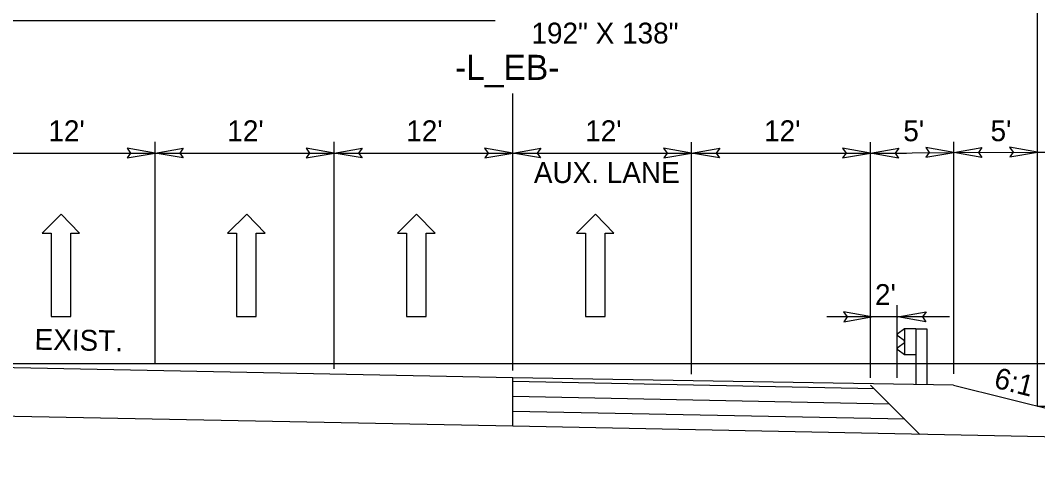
# Model space of a CAD drawing. Extents: x 1727387 to 1728895, y 539219 to 540208.
# Drawn here: x 1727576.9 to 1727645.2, y 539490.3 to 539520.1 of the extents above; entities that cross this region are included whole.
import ezdxf

# ---------------------------------------------------------------- set-up
doc = ezdxf.new("R2010")
doc.units = 0
for name, color, linetype in [('Default', 7, 'Continuous'), ('Prop Dimension Text', 7, 'Continuous'), ('Typical Pavement Slope CELL', 7, 'Continuous'), ('Typical Pavement Slope Information CELL', 7, 'Continuous'), ('Typical Text Centerline CELL', 7, 'Continuous'), ('Typical Text General CELL', 7, 'Continuous')]:
    doc.layers.add(name, color=color, linetype=linetype)

msp = doc.modelspace()

# ---------------------------------------------------------------- linework, layer by layer
at = {"layer": 'Default'}
for p, q in [((1727481.192, 539520.117), (1727608.748, 539520.117)), ((1727609.926, 539496.633), (1727609.926, 539515.213)), ((1727585.93, 539497.114), (1727585.93, 539511.981)), ((1727597.939, 539496.756), (1727597.939, 539511.975)), ((1727609.926, 539496.633), (1727609.926, 539511.975)), ((1727621.935, 539496.393), (1727621.935, 539511.95)), ((1727633.944, 539496.393), (1727633.944, 539511.95)), ((1727633.944, 539496.153), (1727633.944, 539511.95)), ((1727639.53, 539496.417), (1727639.53, 539511.974)), ((1727573.921, 539511.211), (1727585.93, 539511.211)), ((1727585.93, 539511.211), (1727597.939, 539511.211)), ((1727597.939, 539511.211), (1727609.948, 539511.211)), ((1727609.948, 539511.211), (1727621.956, 539511.211)), ((1727621.956, 539511.211), (1727633.965, 539511.211)), ((1727621.956, 539511.211), (1727633.965, 539511.211)), ((1727633.945, 539511.21), (1727639.53, 539511.253)), ((1727633.965, 539511.211), (1727636.345, 539511.211)), ((1727639.57, 539511.246), (1727645.155, 539511.289)), ((1727645.155, 539511.289), (1727661.125, 539511.259)), ((1727579.621, 539507.115), (1727578.341, 539505.855)), ((1727580.861, 539505.855), (1727579.621, 539507.115)), ((1727592.072, 539507.115), (1727590.792, 539505.855)), ((1727593.312, 539505.855), (1727592.072, 539507.115)), ((1727603.472, 539507.115), (1727602.192, 539505.855)), ((1727604.712, 539505.855), (1727603.472, 539507.115)), ((1727615.481, 539507.115), (1727614.201, 539505.855)), ((1727616.721, 539505.855), (1727615.481, 539507.115)), ((1727578.341, 539505.855), (1727578.941, 539505.855)), ((1727578.941, 539505.855), (1727578.941, 539500.255)), ((1727580.261, 539500.255), (1727580.261, 539505.855)), ((1727580.261, 539505.855), (1727580.861, 539505.855)), ((1727590.792, 539505.855), (1727591.392, 539505.855)), ((1727591.392, 539505.855), (1727591.392, 539500.255)), ((1727592.712, 539500.255), (1727592.712, 539505.855)), ((1727592.712, 539505.855), (1727593.312, 539505.855)), ((1727602.192, 539505.855), (1727602.792, 539505.855)), ((1727602.792, 539505.855), (1727602.792, 539500.255)), ((1727604.112, 539500.255), (1727604.112, 539505.855)), ((1727604.112, 539505.855), (1727604.712, 539505.855)), ((1727614.201, 539505.855), (1727614.801, 539505.855)), ((1727614.801, 539505.855), (1727614.801, 539500.255)), ((1727616.121, 539500.255), (1727616.121, 539505.855)), ((1727616.121, 539505.855), (1727616.721, 539505.855)), ((1727635.725, 539496.153), (1727635.725, 539501.028)), ((1727578.941, 539500.255), (1727580.261, 539500.255)), ((1727591.392, 539500.255), (1727592.712, 539500.255)), ((1727602.792, 539500.255), (1727604.112, 539500.255)), ((1727614.801, 539500.255), (1727616.121, 539500.255)), ((1727639.235, 539500.228), (1727630.998, 539500.228)), ((1727653.649, 539497.076), (1727481.192, 539497.076)), ((1727645.155, 539494.248), (1727653.649, 539494.248))]:
    msp.add_line(p, q, dxfattribs=at)
for points in [[(1727584.054, 539510.888), (1727585.93, 539511.211), (1727584.044, 539511.544), (1727584.284, 539511.211)], [(1727587.805, 539510.888), (1727585.93, 539511.211), (1727587.816, 539511.544), (1727587.576, 539511.211)], [(1727596.063, 539510.888), (1727597.939, 539511.211), (1727596.053, 539511.544), (1727596.292, 539511.211)], [(1727599.814, 539510.888), (1727597.939, 539511.211), (1727599.825, 539511.544), (1727599.585, 539511.211)], [(1727608.05, 539510.888), (1727609.926, 539511.211), (1727608.04, 539511.544), (1727608.279, 539511.211)], [(1727611.801, 539510.888), (1727609.926, 539511.211), (1727611.812, 539511.544), (1727611.572, 539511.211)], [(1727620.059, 539510.888), (1727621.935, 539511.211), (1727620.049, 539511.544), (1727620.288, 539511.211)], [(1727623.81, 539510.888), (1727621.935, 539511.211), (1727623.821, 539511.544), (1727623.581, 539511.211)], [(1727632.068, 539510.888), (1727633.944, 539511.211), (1727632.058, 539511.544), (1727632.297, 539511.211)], [(1727635.821, 539510.887), (1727633.945, 539511.21), (1727635.831, 539511.544), (1727635.592, 539511.21)], [(1727637.651, 539510.935), (1727639.527, 539511.258), (1727637.641, 539511.591), (1727637.88, 539511.258)], [(1727641.406, 539510.93), (1727639.53, 539511.253), (1727641.416, 539511.586), (1727641.177, 539511.253)], [(1727643.279, 539510.966), (1727645.155, 539511.289), (1727643.269, 539511.622), (1727643.509, 539511.289)], [(1727632.139, 539499.905), (1727634.014, 539500.228), (1727632.128, 539500.562), (1727632.368, 539500.228)], [(1727637.659, 539499.905), (1727635.783, 539500.228), (1727637.669, 539500.562), (1727637.429, 539500.228)]]:
    msp.add_lwpolyline(points, close=True, dxfattribs=at)
at = {"layer": 'Typical Pavement Slope CELL'}
for p, q in [((1727609.926, 539496.14), (1727563.08, 539497.076)), ((1727609.926, 539492.892), (1727609.926, 539496.14)), ((1727639.512, 539495.659), (1727609.926, 539496.14)), ((1727634.195, 539495.407), (1727609.926, 539495.893)), ((1727633.944, 539495.659), (1727637.258, 539492.345)), ((1727639.512, 539495.659), (1727661.124, 539490.256)), ((1727635.215, 539494.387), (1727609.926, 539494.893)), ((1727597.268, 539493.145), (1727563.08, 539493.829)), ((1727636.236, 539493.366), (1727609.926, 539493.892)), ((1727609.926, 539492.892), (1727597.268, 539493.145)), ((1727654.117, 539492.008), (1727609.926, 539492.892))]:
    msp.add_line(p, q, dxfattribs=at)
at = {"layer": 'Typical Text Centerline CELL'}
msp.add_line((1727645.155, 539494.248), (1727645.155, 539527.667), dxfattribs=at)
at = {"layer": 'Typical Text General CELL'}
for p, q in [((1727636.223, 539499.432), (1727635.789, 539499.127)), ((1727636.97, 539499.432), (1727636.223, 539499.432)), ((1727636.223, 539499.432), (1727636.223, 539497.691)), ((1727636.97, 539499.432), (1727636.97, 539495.7)), ((1727636.97, 539499.432), (1727637.716, 539499.432)), ((1727637.716, 539499.432), (1727637.716, 539495.7)), ((1727636.223, 539498.631), (1727635.789, 539498.936)), ((1727636.223, 539498.561), (1727636.223, 539498.631)), ((1727636.223, 539498.561), (1727636.223, 539498.491)), ((1727636.223, 539498.491), (1727635.789, 539498.186)), ((1727636.223, 539497.691), (1727635.789, 539497.995)), ((1727636.97, 539497.691), (1727636.223, 539497.691))]:
    msp.add_line(p, q, dxfattribs=at)
for centre, start, end in [((1727635.855, 539499.031), 125.00297, 235.0112), ((1727635.855, 539498.091), 125.0059, 235.0366)]:
    msp.add_arc(centre, 0.117, start, end, dxfattribs=at)

# ---------------------------------------------------------------- texts
at = {"layer": 'Prop Dimension Text'}
msp.add_text("5'", height=1.401, dxfattribs=at).set_placement((1727641.995, 539512.016))
msp.add_text('6:1', height=1.401, rotation=345.96376, dxfattribs=at).set_placement((1727642.152, 539495.505))
at = {"layer": 'Typical Pavement Slope Information CELL'}
for s, height, p in [('192" X 138"', 1.40103, (1727611.182, 539518.563)), ("12'", 1.401, (1727578.763, 539512.011)), ("12'", 1.401, (1727590.772, 539512.011)), ("12'", 1.401, (1727602.781, 539512.011)), ("12'", 1.401, (1727614.79, 539512.011)), ("12'", 1.401, (1727626.798, 539512.011)), ("5'", 1.401, (1727636.14, 539512.011)), ('AUX. LANE', 1.401, (1727611.347, 539509.209)), ("2'", 1.401, (1727634.241, 539501.028))]:
    msp.add_text(s, height=height, dxfattribs=at).set_placement(p)
msp.add_text('EXIST.', height=1.401, rotation=358.85426, dxfattribs=at).set_placement((1727577.823, 539498.033))
at = {"layer": 'Typical Text Centerline CELL'}
msp.add_text('-L_EB-', height=1.6842, dxfattribs=at).set_placement((1727606.054, 539516.123))

doc.saveas('drawing.dxf')
